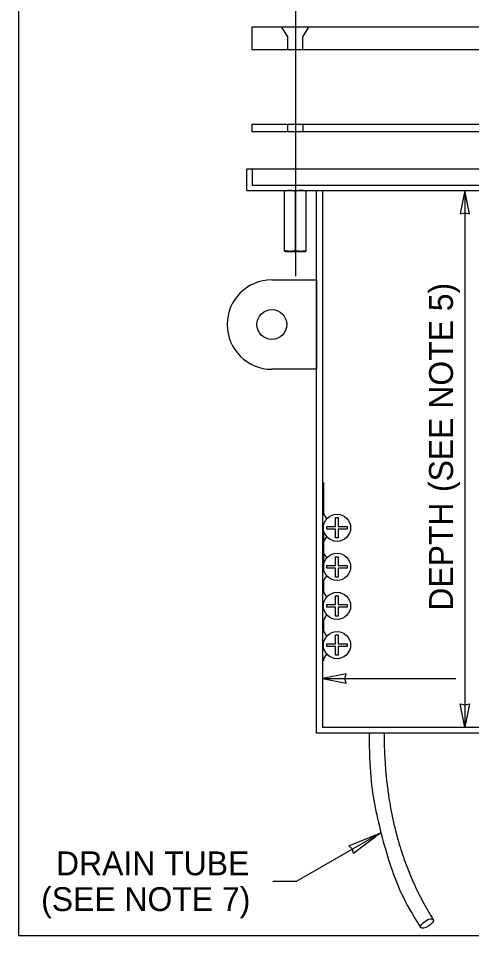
# Model space of a CAD drawing. Extents: x 99862 to 103680, y 99470 to 102076.
# Drawn here: x 99862 to 100166, y 100000 to 100615 of the extents above; entities that cross this region are included whole.
import ezdxf

# ---------------------------------------------------------------- set-up
doc = ezdxf.new("R2010")
doc.units = 0
for name, color, linetype in [('Level 1', 7, 'Continuous'), ('Level 10', 7, 'Continuous'), ('Level 14', 7, 'Continuous'), ('Level 15', 7, 'Continuous'), ('Level 16', 7, 'Continuous'), ('Level 2', 7, 'Continuous'), ('Level 20', 7, 'Continuous'), ('Level 6', 7, 'Continuous'), ('Level 60', 7, 'Continuous'), ('Level 7', 7, 'Continuous')]:
    doc.layers.add(name, color=color, linetype=linetype)

msp = doc.modelspace()

# ---------------------------------------------------------------- linework, layer by layer
at = {"layer": 'Level 1'}
for p, q in [((100015.12, 100513.87), (100579.84, 100513.87)), ((100015.12, 100499.41), (100015.12, 100513.87)), ((100018.69, 100513.87), (100018.69, 100502.97)), ((100015.12, 100499.41), (100579.84, 100499.41)), ((100018.69, 100502.97), (100576.28, 100502.97)), ((100061.98, 100135.35), (100061.98, 100499.41)), ((100065.98, 100499.41), (100065.98, 100139.35)), ((100532.98, 100135.35), (100061.98, 100135.35)), ((100065.98, 100139.35), (100528.98, 100139.35))]:
    msp.add_line(p, q, dxfattribs=at)
msp.add_lwpolyline([(99862, 99999.5), (103151, 99999.5), (103151, 102075.5), (99862, 102075.5)], close=True, dxfattribs=at)
msp.add_lwpolyline([(99862, 99999.5), (103151, 99999.5), (103151, 102075.5), (99862, 102075.5)], close=True, dxfattribs=at)
msp.add_lwpolyline([(99862, 99999.5), (103151, 99999.5), (103151, 102075.5), (99862, 102075.5)], close=True, dxfattribs=at)
at = {"layer": 'Level 10'}
for p, q in [((100041.22, 100499.41), (100040.45, 100499.2)), ((100041.22, 100499.41), (100040.45, 100499.2)), ((100041.22, 100499.41), (100040.45, 100499.2)), ((100041.22, 100499.41), (100040.45, 100499.2)), ((100040.45, 100458.9), (100040.45, 100498.89)), ((100041.22, 100499.41), (100047.72, 100499.41)), ((100047.72, 100499.41), (100054.22, 100499.41)), ((100047.72, 100458.9), (100047.72, 100498.89)), ((100054.98, 100499.2), (100054.22, 100499.41)), ((100054.98, 100499.2), (100054.22, 100499.41)), ((100054.98, 100499.2), (100054.22, 100499.41)), ((100054.98, 100499.2), (100054.22, 100499.41)), ((100054.98, 100458.9), (100054.98, 100498.89)), ((100040.45, 100458.59), (100041.22, 100458.37)), ((100041.22, 100458.37), (100054.22, 100458.37)), ((100054.22, 100458.37), (100054.98, 100458.59))]:
    msp.add_line(p, q, dxfattribs=at)
for points in [[(100074.73, 100274.04), (100074.73, 100279.9), (100076.52, 100279.9), (100076.52, 100274.04)], [(100074.73, 100272.25), (100068.82, 100272.25), (100068.82, 100274.04), (100074.73, 100274.04)], [(100076.52, 100272.25), (100076.52, 100266.24), (100074.73, 100266.24), (100074.73, 100272.25)], [(100076.52, 100274.04), (100082.48, 100274.04), (100082.48, 100272.25), (100076.52, 100272.25)], [(100074.73, 100247.8), (100074.73, 100253.67), (100076.52, 100253.67), (100076.52, 100247.8)], [(100074.73, 100246.01), (100068.82, 100246.01), (100068.82, 100247.8), (100074.73, 100247.8)], [(100076.52, 100246.01), (100076.52, 100240), (100074.73, 100240), (100074.73, 100246.01)], [(100076.52, 100247.8), (100082.48, 100247.8), (100082.48, 100246.01), (100076.52, 100246.01)], [(100074.73, 100221.57), (100074.73, 100227.43), (100076.52, 100227.43), (100076.52, 100221.57)], [(100074.73, 100219.78), (100068.82, 100219.78), (100068.82, 100221.57), (100074.73, 100221.57)], [(100076.52, 100221.57), (100082.48, 100221.57), (100082.48, 100219.78), (100076.52, 100219.78)], [(100076.52, 100219.78), (100076.52, 100213.77), (100074.73, 100213.77), (100074.73, 100219.78)], [(100074.73, 100195.34), (100074.73, 100201.2), (100076.52, 100201.2), (100076.52, 100195.34)], [(100074.73, 100193.55), (100068.82, 100193.55), (100068.82, 100195.34), (100074.73, 100195.34)], [(100076.52, 100193.55), (100076.52, 100187.54), (100074.73, 100187.54), (100074.73, 100193.55)], [(100076.52, 100195.34), (100082.48, 100195.34), (100082.48, 100193.55), (100076.52, 100193.55)]]:
    msp.add_lwpolyline(points, dxfattribs=at)
for centre in [(100075.65, 100273.14), (100075.65, 100246.91), (100075.65, 100220.67), (100075.65, 100194.44)]:
    msp.add_circle(centre, 9.15, dxfattribs=at)
for points in [[(100047.72, 100498.89), (100045.3, 100499.31), (100042.87, 100499.3), (100040.45, 100498.89)], [(100040.45, 100498.89), (100040.45, 100498.99), (100040.45, 100499.09), (100040.45, 100499.19)], [(100054.98, 100498.89), (100052.56, 100499.31), (100050.14, 100499.3), (100047.72, 100498.89)], [(100054.98, 100499.2), (100054.98, 100499.09), (100054.98, 100498.99), (100054.98, 100498.89)], [(100040.45, 100458.9), (100040.45, 100458.8), (100040.45, 100458.69), (100040.45, 100458.59)], [(100047.72, 100458.9), (100045.3, 100458.47), (100042.87, 100458.48), (100040.45, 100458.9)], [(100054.98, 100458.9), (100052.56, 100458.47), (100050.14, 100458.48), (100047.72, 100458.9)]]:
    msp.add_open_spline(points, degree=2, dxfattribs=at)
at = {"layer": 'Level 14'}
msp.add_ellipse((100135.95, 100007.64), major_axis=(4.23, 2.67), ratio=0.398386, dxfattribs=at)
for points, degree in [([(100097.23, 100135.35), (100097.23, 100110.33), (100100.06, 100086.91), (100111.53, 100043.38), (100120.18, 100023.28), (100131.72, 100004.97)], 3), ([(100107.23, 100135.35), (100107.23, 100062.56), (100140.18, 100010.31)], 2)]:
    msp.add_open_spline(points, degree=degree, dxfattribs=at)
at = {"layer": 'Level 15'}
for p, q in [((100047.72, 100664.75), (100047.72, 100441.8)), ((100161.38, 100499.41), (100161.38, 100139.35)), ((100065.98, 100172.06), (100155.38, 100172.06)), ((100104.94, 100068.51), (100048.65, 100036.01)), ((100032.65, 100036.01), (100048.65, 100036.01))]:
    msp.add_line(p, q, dxfattribs=at)
for points in [[(100161.38, 100499.41), (100158.3, 100483.69), (100161.38, 100484.41), (100164.47, 100483.69)], [(100065.98, 100172.06), (100081.71, 100168.97), (100080.98, 100172.06), (100081.71, 100175.14)], [(100161.38, 100139.35), (100158.3, 100155.07), (100161.38, 100154.34), (100164.47, 100155.07)], [(100104.94, 100068.51), (100086.66, 100054.51), (100086.08, 100057.62), (100083.68, 100059.68)]]:
    msp.add_lwpolyline(points, close=True, dxfattribs=at)
at = {"layer": 'Level 16'}
for p, q in [((100018.55, 100608.82), (100018.55, 100593.82)), ((100575.99, 100608.82), (100018.55, 100608.82)), ((100042.72, 100602.38), (100038.56, 100608.83)), ((100052.72, 100602.38), (100056.87, 100608.83)), ((100042.72, 100593.82), (100042.72, 100602.38)), ((100052.72, 100593.82), (100052.72, 100602.38)), ((100018.55, 100593.82), (100575.99, 100593.82))]:
    msp.add_line(p, q, dxfattribs=at)
at = {"layer": 'Level 2'}
for p, q in [((100018.55, 100543.78), (100575.99, 100543.78)), ((100018.55, 100543.78), (100018.55, 100538.78)), ((100042.72, 100538.78), (100042.72, 100543.78)), ((100052.72, 100543.78), (100052.72, 100538.78)), ((100575.99, 100538.78), (100018.55, 100538.78))]:
    msp.add_line(p, q, dxfattribs=at)
at = {"layer": 'Level 6'}
for p, q in [((100031.98, 100439.41), (100061.98, 100439.41)), ((100061.98, 100439.41), (100061.98, 100379.41)), ((100061.98, 100379.41), (100031.98, 100379.41))]:
    msp.add_line(p, q, dxfattribs=at)
msp.add_circle((100031.98, 100409.41), 10, dxfattribs=at)
msp.add_arc((100031.98, 100409.41), 30, 90, 270, dxfattribs=at)
at = {"layer": 'Level 60'}
msp.add_line((99862, 99999.5), (99862, 99999.5), dxfattribs=at)
msp.add_line((99862, 99999.5), (99862, 99999.5), dxfattribs=at)
msp.add_line((99862, 99999.5), (99862, 99999.5), dxfattribs=at)
at = {"layer": 'Level 7'}
for p, q in [((100066.5, 100303.51), (100066.5, 100283.74)), ((100066.5, 100270.64), (100066.5, 100244.35)), ((100066.5, 100262.54), (100066.5, 100257.51)), ((100066.5, 100236.31), (100066.5, 100231.27)), ((100066.5, 100210.07), (100066.5, 100205.04))]:
    msp.add_line(p, q, dxfattribs=at)
for centre, start, end in [((100071.5, 100283.74), 180, 239.86335), ((100071.5, 100262.54), 120.13665, 180), ((100071.5, 100257.51), 180, 239.86335), ((100071.5, 100236.31), 120.13665, 180), ((100071.5, 100231.27), 180, 239.86335), ((100071.5, 100210.07), 120.13665, 180), ((100071.5, 100205.04), 180, 239.86335), ((100071.5, 100183.84), 120.13665, 180)]:
    msp.add_arc(centre, 5, start, end, dxfattribs=at)

# ---------------------------------------------------------------- texts
at = {"layer": 'Level 20'}
for s, p in [(' (SEE NOTE 5)', (100153.38, 100291.13)), ('DEPTH', (100153.38, 100217.48))]:
    msp.add_text(s, height=16, rotation=90, dxfattribs=at).set_placement(p)
for s, p in [('DRAIN TUBE', (99887.25, 100040.01)), ('(SEE NOTE 7)', (99877.27, 100016.01))]:
    msp.add_text(s, height=16, dxfattribs=at).set_placement(p)

doc.saveas('drawing.dxf')
